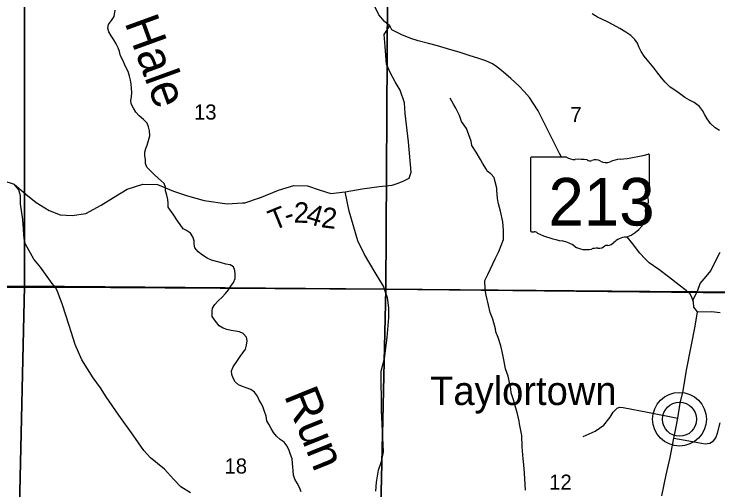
# Model space of a CAD drawing. Extents: x 2.1 to 8.9, y 14.1 to 20.9.
# Drawn here: x 3.51 to 5.459, y 18.588 to 19.907 of the extents above; entities that cross this region are included whole.
import ezdxf

# ---------------------------------------------------------------- set-up
doc = ezdxf.new("R2010")
doc.units = 0
for name, color, linetype in [('Default', 7, 'Continuous'), ('GM_X_City_Street', 7, 'Continuous'), ('GM_X_County_Road', 7, 'Continuous'), ('GM_X_County_Road_Text', 7, 'Continuous'), ('GM_X_Interchange_Ramps', 7, 'Continuous'), ('GM_X_Major_River', 7, 'Continuous'), ('GM_X_Minor_River_Text', 7, 'Continuous'), ('GM_X_Rail_Line_Text', 7, 'Continuous'), ('GM_X_Section_Text', 7, 'Continuous'), ('GM_X_State_Route', 7, 'Continuous'), ('GM_X_State_Shield', 7, 'Continuous'), ('GM_X_Township_Text', 7, 'Continuous'), ('PV_P_Text', 7, 'Continuous'), ('TX_P_Misc', 7, 'Continuous')]:
    doc.layers.add(name, color=color, linetype=linetype)

msp = doc.modelspace()

# ---------------------------------------------------------------- linework, layer by layer
at = {"layer": 'Default'}
for p, q in [((3.624, 19.1497), (2.7675, 19.1488)), ((2.7675, 19.1488), (3.624, 19.1497)), ((4.5355, 19.1447), (3.624, 19.1497)), ((3.624, 19.1497), (4.5355, 19.1447)), ((5.3758, 19.1372), (4.5355, 19.1447)), ((4.5355, 19.1447), (5.3758, 19.1372)), ((5.4005, 19.1369), (5.3758, 19.1372)), ((5.3758, 19.1372), (5.4005, 19.1369)), ((6.8944, 19.1204), (5.4005, 19.1369)), ((5.4005, 19.1369), (6.8944, 19.1204))]:
    msp.add_line(p, q, dxfattribs=at)
at = {"layer": 'GM_X_City_Street'}
for p, q in [((4.5343, 19.85), (4.5505, 19.8741)), ((4.5377, 19.8167), (4.5343, 19.85)), ((4.5414, 19.7683), (4.5377, 19.8167)), ((4.5515, 19.7444), (4.5414, 19.7683)), ((4.5655, 19.7188), (4.5515, 19.7444)), ((4.579, 19.6959), (4.5655, 19.7188)), ((4.5912, 19.6607), (4.579, 19.6959)), ((4.5924, 19.6316), (4.5912, 19.6607)), ((4.602, 19.553), (4.5924, 19.6316)), ((4.6091, 19.4686), (4.602, 19.553)), ((4.6042, 19.4521), (4.6091, 19.4686)), ((3.4788, 19.4459), (3.5099, 19.4359)), ((3.5099, 19.4359), (3.5418, 19.4081)), ((3.5231, 19.4198), (3.5099, 19.4359)), ((3.823, 19.422), (3.8666, 19.4357)), ((3.8666, 19.4357), (3.9068, 19.4345)), ((3.9068, 19.4345), (3.9511, 19.4163)), ((4.5563, 19.4329), (4.5738, 19.4382)), ((4.5738, 19.4382), (4.589, 19.4446)), ((4.589, 19.4446), (4.6042, 19.4521)), ((3.5277, 19.4029), (3.5231, 19.4198)), ((3.7854, 19.3983), (3.823, 19.422)), ((3.9511, 19.4163), (3.9902, 19.4028)), ((4.1905, 19.3977), (4.2418, 19.4186)), ((4.2418, 19.4186), (4.2847, 19.4319)), ((4.2847, 19.4319), (4.3222, 19.4305)), ((4.3222, 19.4305), (4.3545, 19.4194)), ((4.3545, 19.4194), (4.3867, 19.4098)), ((4.4266, 19.4138), (4.4739, 19.4224)), ((4.4739, 19.4224), (4.5205, 19.429)), ((4.5205, 19.429), (4.5563, 19.4329)), ((3.5279, 19.3809), (3.5277, 19.4029)), ((3.5418, 19.4081), (3.5708, 19.385)), ((3.7508, 19.3774), (3.7854, 19.3983)), ((3.9902, 19.4028), (4.0365, 19.3905)), ((4.1484, 19.3837), (4.1896, 19.3974)), ((4.1896, 19.3974), (4.1905, 19.3977)), ((4.3867, 19.4098), (4.4266, 19.4138)), ((4.438, 19.3608), (4.4266, 19.4138)), ((3.5341, 19.3377), (3.5279, 19.3809)), ((3.5708, 19.385), (3.6066, 19.3627)), ((3.7083, 19.3543), (3.7508, 19.3774)), ((4.0365, 19.3905), (4.0998, 19.3807)), ((4.0998, 19.3807), (4.1426, 19.3833)), ((4.1426, 19.3833), (4.1484, 19.3837)), ((3.6066, 19.3627), (3.6374, 19.3508)), ((4.4614, 19.2783), (4.438, 19.3608)), ((3.5372, 19.2839), (3.5341, 19.3377)), ((3.6374, 19.3508), (3.6708, 19.3485)), ((3.6708, 19.3485), (3.7083, 19.3543)), ((3.5417, 19.2696), (3.5372, 19.2839)), ((4.4801, 19.2408), (4.4614, 19.2783)), ((3.5643, 19.2279), (3.5417, 19.2696)), ((4.5099, 19.1908), (4.4801, 19.2408)), ((5.4511, 19.2205), (5.4655, 19.2473)), ((3.5824, 19.2053), (3.5643, 19.2279)), ((5.439, 19.1957), (5.4511, 19.2205)), ((3.6155, 19.1603), (3.5824, 19.2053)), ((4.5327, 19.1531), (4.5099, 19.1908)), ((5.4265, 19.1795), (5.439, 19.1957)), ((5.41, 19.1598), (5.4265, 19.1795)), ((3.6242, 19.1492), (3.6155, 19.1603)), ((3.6251, 19.1475), (3.6242, 19.1492)), ((3.6286, 19.1408), (3.6251, 19.1475)), ((4.5357, 19.1442), (4.5327, 19.1531)), ((4.5437, 19.1202), (4.5357, 19.1442)), ((5.4022, 19.1393), (5.41, 19.1598)), ((3.6442, 19.1012), (3.6286, 19.1408)), ((5.3893, 19.1136), (5.3985, 19.132)), ((5.3985, 19.132), (5.4007, 19.1364)), ((5.4007, 19.1364), (5.4022, 19.1393)), ((4.5456, 19.1077), (4.5437, 19.1202)), ((4.5479, 19.0923), (4.5456, 19.1077)), ((3.6623, 19.0436), (3.6442, 19.1012)), ((4.5472, 19.0657), (4.5479, 19.0923)), ((4.5425, 19.0104), (4.5472, 19.0657)), ((3.6789, 18.9911), (3.6623, 19.0436)), ((4.5352, 18.9523), (4.5425, 19.0104)), ((3.6974, 18.9488), (3.6789, 18.9911)), ((3.7288, 18.8988), (3.6974, 18.9488)), ((4.5262, 18.9174), (4.5352, 18.9523)), ((4.5268, 18.8092), (4.5262, 18.9174)), ((3.7486, 18.8714), (3.7288, 18.8988)), ((3.7645, 18.8465), (3.7486, 18.8714)), ((3.7994, 18.7953), (3.7645, 18.8465)), ((5.1686, 18.8038), (5.1794, 18.8148)), ((5.1794, 18.8148), (5.1861, 18.8177)), ((5.1861, 18.8177), (5.1964, 18.8164)), ((5.1964, 18.8164), (5.264, 18.8035)), ((3.8396, 18.7396), (3.7994, 18.7953)), ((4.5327, 18.6939), (4.5268, 18.8092)), ((5.1606, 18.7902), (5.1686, 18.8038)), ((5.264, 18.8035), (5.3482, 18.7874)), ((5.1431, 18.768), (5.1606, 18.7902)), ((5.458, 18.7457), (5.4649, 18.7745)), ((5.1185, 18.7508), (5.1431, 18.768)), ((3.8689, 18.6973), (3.8396, 18.7396)), ((5.086, 18.7361), (5.1185, 18.7508)), ((5.3368, 18.7319), (5.3784, 18.7243)), ((5.4463, 18.7239), (5.4534, 18.7323)), ((5.4534, 18.7323), (5.458, 18.7457)), ((5.3784, 18.7243), (5.4036, 18.7194)), ((5.4036, 18.7194), (5.4232, 18.7162)), ((5.4232, 18.7162), (5.4366, 18.7179)), ((5.4366, 18.7179), (5.4463, 18.7239)), ((3.8879, 18.6771), (3.8689, 18.6973)), ((4.5276, 18.6674), (4.5327, 18.6939)), ((3.9259, 18.6462), (3.8879, 18.6771)), ((4.5193, 18.6431), (4.5276, 18.6674)), ((3.9509, 18.618), (3.9259, 18.6462)), ((4.5132, 18.6095), (4.5193, 18.6431)), ((3.9711, 18.5969), (3.9509, 18.618)), ((3.998, 18.5798), (3.9711, 18.5969)), ((4.5117, 18.5848), (4.5132, 18.6095))]:
    msp.add_line(p, q, dxfattribs=at)
at = {"layer": 'GM_X_County_Road'}
for p, q in [((5.2696, 19.4105), (5.2696, 19.5152)), ((4.94, 19.5068), (4.94, 19.3066)), ((5.0398, 19.5102), (4.9432, 19.5102)), ((5.2695, 19.4105), (5.2696, 19.4105))]:
    msp.add_line(p, q, dxfattribs=at)
for centre, major_axis, start_param, end_param in [((5.1522, 19.783), (0.3495, 0), 4.814394, 5.042369), ((5.2659, 19.5156), (0.00367, 0), 6.141152, 7.989035), ((4.9438, 19.5072), (0.00382, 0), 1.712693, 3.28349), ((5.0627, 19.5334), (0.037, 0), 4.042523, 4.731795), ((5.075, 19.3979), (0.133, 0), 1.404758, 1.657858), ((5.1052, 19.5082), (0.0107, 0), 3.836095, 5.185415), ((5.1209, 19.4851), (0.0222, 0), 0.950623, 2.079405), ((5.1496, 19.5168), (0.0267, 0), 4.081561, 5.145723), ((5.1968, 19.4491), (0.0703, 0), 1.699011, 2.107814), ((5.2687, 19.4028), (0.00568, 0), 1.883978, 3.671073), ((5.2326, 19.3896), (0.0341, 0), 5.934695, 6.695948), ((5.2657, 19.4101), (0.00393, 0), 5.05454, 6.418171), ((5.2827, 19.3667), (0.0248, 0), 2.387724, 3.262537), ((5.1717, 19.3533), (0.0874, 0), 5.101752, 6.440018), ((4.9438, 19.3062), (0.00385, 0), 3.00124, 4.508301), ((4.9444, 19.3267), (0.0294, 0), 4.665946, 4.897461), ((4.9504, 19.2951), (0.0106, 0), 0.519207, 1.627899), ((5.0842, 19.4749), (0.2524, 0), 4.195997, 4.488961), ((5.009, 19.2167), (0.079, 0), 0.823519, 1.323587), ((5.2086, 19.2505), (0.0479, 0), 1.647645, 2.488434), ((5.0944, 19.2941), (0.0501, 0), 4.026481, 4.996735), ((5.127, 19.2791), (0.0267, 0), 4.691044, 5.507374), ((5.1512, 19.2597), (0.00752, 0), 1.147584, 2.315152), ((5.1479, 19.2872), (0.0282, 0), 4.937069, 5.64225), ((5.1233, 19.2249), (0.0412, 0), 1.495662, 1.94098)]:
    msp.add_ellipse(centre, major_axis=major_axis, ratio=0.8, start_param=start_param, end_param=end_param, dxfattribs=at)
at = {"layer": 'GM_X_Interchange_Ramps'}
for p, q in [((3.5383, 20.1501), (3.5387, 19.1524)), ((3.5387, 19.1524), (3.5383, 20.1501)), ((4.5449, 20.1449), (4.5388, 19.1444)), ((4.5388, 19.1444), (4.5449, 20.1449)), ((3.5387, 19.1524), (2.5274, 19.148)), ((2.5274, 19.148), (3.5387, 19.1524)), ((3.5387, 19.1524), (3.5154, 18.1224)), ((3.5154, 18.1224), (3.5387, 19.1524)), ((4.5388, 19.1444), (3.5387, 19.1524)), ((3.5387, 19.1524), (4.5388, 19.1444)), ((4.5388, 19.1444), (4.5166, 18.1148)), ((4.5166, 18.1148), (4.5388, 19.1444)), ((5.5458, 19.1336), (4.5388, 19.1444)), ((4.5388, 19.1444), (5.5458, 19.1336))]:
    msp.add_line(p, q, dxfattribs=at)
at = {"layer": 'GM_X_Rail_Line_Text'}
for p, q in [((4.5194, 19.9047), (4.4987, 19.9491)), ((4.5357, 19.8864), (4.5194, 19.9047)), ((4.5505, 19.8741), (4.5357, 19.8864)), ((4.5554, 19.8631), (4.5505, 19.8741)), ((4.5837, 19.8496), (4.5554, 19.8631)), ((4.6085, 19.8394), (4.5837, 19.8496)), ((4.6284, 19.8326), (4.6085, 19.8394)), ((4.6574, 19.8248), (4.6284, 19.8326)), ((4.6821, 19.8184), (4.6574, 19.8248)), ((4.7103, 19.8103), (4.6821, 19.8184)), ((4.7447, 19.7999), (4.7103, 19.8103)), ((4.7725, 19.791), (4.7447, 19.7999)), ((4.7943, 19.7846), (4.7725, 19.791)), ((4.816, 19.7774), (4.7943, 19.7846)), ((4.8348, 19.7686), (4.816, 19.7774)), ((4.8467, 19.7601), (4.8348, 19.7686)), ((4.8655, 19.7457), (4.8467, 19.7601)), ((4.8856, 19.7286), (4.8655, 19.7457)), ((4.9084, 19.707), (4.8856, 19.7286)), ((4.9227, 19.6918), (4.9084, 19.707)), ((4.9367, 19.6753), (4.9227, 19.6918)), ((4.9476, 19.66), (4.9367, 19.6753)), ((4.9609, 19.6382), (4.9476, 19.66)), ((4.9778, 19.6055), (4.9609, 19.6382)), ((5.0011, 19.5593), (4.9778, 19.6055)), ((5.02, 19.5205), (5.0011, 19.5593)), ((5.0253, 19.5102), (5.02, 19.5205)), ((5.2224, 19.2709), (5.2072, 19.2894)), ((5.243, 19.2439), (5.2224, 19.2709)), ((5.2573, 19.2283), (5.243, 19.2439)), ((5.2689, 19.2179), (5.2573, 19.2283)), ((5.295, 19.1986), (5.2689, 19.2179)), ((5.3216, 19.1787), (5.295, 19.1986)), ((5.3516, 19.1557), (5.3216, 19.1787)), ((5.3712, 19.1409), (5.3516, 19.1557)), ((5.376, 19.1366), (5.3712, 19.1409)), ((5.3809, 19.1324), (5.376, 19.1366)), ((5.3867, 19.1226), (5.3809, 19.1324)), ((5.3893, 19.1136), (5.3867, 19.1226)), ((5.3908, 19.1083), (5.3893, 19.1136)), ((5.3926, 19.0942), (5.3908, 19.1083)), ((5.4022, 19.0815), (5.3926, 19.0942)), ((5.3956, 19.0421), (5.4022, 19.0815)), ((5.385, 18.9861), (5.3956, 19.0421)), ((5.372, 18.9201), (5.385, 18.9861)), ((5.3624, 18.8625), (5.372, 18.9201)), ((5.3545, 18.8288), (5.3624, 18.8625)), ((5.3482, 18.7874), (5.3545, 18.8288)), ((5.3422, 18.7584), (5.3482, 18.7874)), ((5.3368, 18.7319), (5.3422, 18.7584)), ((5.3262, 18.6778), (5.3368, 18.7319)), ((5.3153, 18.63), (5.3262, 18.6778)), ((5.304, 18.5723), (5.3153, 18.63))]:
    msp.add_line(p, q, dxfattribs=at)
at = {"layer": 'GM_X_State_Route'}
for radius in [0.0744, 0.0472]:
    msp.add_circle((5.3524, 18.7841), radius, dxfattribs=at)
at = {"layer": 'GM_X_State_Shield'}
for p, q in [((5.4022, 19.0815), (5.441, 19.0825)), ((5.441, 19.0825), (5.4647, 19.0796))]:
    msp.add_line(p, q, dxfattribs=at)
at = {"layer": 'GM_X_Township_Text'}
msp.add_line((5.3524, 18.7841), (5.3524, 18.7841), dxfattribs=at)
at = {"layer": 'TX_P_Misc'}
for p, q in [((3.7871, 19.9004), (3.7896, 19.9176)), ((5.1255, 19.8986), (5.1104, 19.9072)), ((3.7715, 19.8778), (3.7799, 19.8887)), ((3.7799, 19.8887), (3.7871, 19.9004)), ((5.139, 19.8918), (5.1255, 19.8986)), ((5.1529, 19.8854), (5.139, 19.8918)), ((5.1692, 19.8767), (5.1529, 19.8854)), ((3.7695, 19.8679), (3.7715, 19.8778)), ((3.7725, 19.8577), (3.7695, 19.8679)), ((5.1874, 19.8667), (5.1692, 19.8767)), ((5.2036, 19.8569), (5.1874, 19.8667)), ((3.7786, 19.8461), (3.7725, 19.8577)), ((3.7858, 19.8353), (3.7786, 19.8461)), ((5.2176, 19.8475), (5.2036, 19.8569)), ((5.229, 19.8364), (5.2176, 19.8475)), ((3.7922, 19.8241), (3.7858, 19.8353)), ((3.7975, 19.8129), (3.7922, 19.8241)), ((5.2358, 19.8264), (5.229, 19.8364)), ((5.2403, 19.8159), (5.2358, 19.8264)), ((3.8012, 19.8027), (3.7975, 19.8129)), ((5.246, 19.8027), (5.2403, 19.8159)), ((3.8046, 19.791), (3.8012, 19.8027)), ((3.8111, 19.7791), (3.8046, 19.791)), ((5.2544, 19.7901), (5.246, 19.8027)), ((5.2674, 19.7741), (5.2544, 19.7901)), ((3.8156, 19.7678), (3.8111, 19.7791)), ((3.8205, 19.7581), (3.8156, 19.7678)), ((5.2813, 19.7574), (5.2674, 19.7741)), ((3.8254, 19.7476), (3.8205, 19.7581)), ((3.8292, 19.7351), (3.8254, 19.7476)), ((5.2928, 19.7426), (5.2813, 19.7574)), ((3.8318, 19.7238), (3.8292, 19.7351)), ((5.3023, 19.7304), (5.2928, 19.7426)), ((5.3129, 19.7178), (5.3023, 19.7304)), ((3.8337, 19.7121), (3.8318, 19.7238)), ((3.8352, 19.7019), (3.8337, 19.7121)), ((5.3267, 19.7045), (5.3129, 19.7178)), ((3.8348, 19.6771), (3.836, 19.6893)), ((3.836, 19.6893), (3.8352, 19.7019)), ((5.3426, 19.6936), (5.3267, 19.7045)), ((5.3558, 19.6837), (5.3426, 19.6936)), ((3.8332, 19.6676), (3.8348, 19.6771)), ((3.8343, 19.6577), (3.8332, 19.6676)), ((4.7268, 19.657), (4.7171, 19.6739)), ((5.3675, 19.6754), (5.3558, 19.6837)), ((5.3803, 19.6685), (5.3675, 19.6754)), ((5.3934, 19.6617), (5.3803, 19.6685)), ((3.84, 19.6461), (3.8343, 19.6577)), ((4.7327, 19.6457), (4.7268, 19.657)), ((5.4082, 19.6508), (5.3934, 19.6617)), ((5.4165, 19.64), (5.4082, 19.6508)), ((3.8471, 19.6353), (3.84, 19.6461)), ((3.8562, 19.6246), (3.8471, 19.6353)), ((4.7429, 19.6257), (4.7327, 19.6457)), ((5.423, 19.6273), (5.4165, 19.64)), ((3.868, 19.6143), (3.8562, 19.6246)), ((3.8785, 19.6043), (3.868, 19.6143)), ((4.7492, 19.6095), (4.7429, 19.6257)), ((4.7624, 19.5895), (4.7492, 19.6095)), ((5.4287, 19.6161), (5.423, 19.6273)), ((5.4382, 19.6038), (5.4287, 19.6161)), ((3.8823, 19.5942), (3.8785, 19.6043)), ((3.8845, 19.5836), (3.8823, 19.5942)), ((4.7755, 19.5548), (4.7624, 19.5895)), ((5.4511, 19.5917), (5.4382, 19.6038)), ((5.4631, 19.5837), (5.4511, 19.5917)), ((3.8853, 19.5692), (3.8845, 19.5836)), ((3.8778, 19.5439), (3.8816, 19.5561)), ((3.8816, 19.5561), (3.8853, 19.5692)), ((4.7776, 19.5427), (4.7755, 19.5548)), ((3.8715, 19.5243), (3.8746, 19.5343)), ((3.8746, 19.5343), (3.8778, 19.5439)), ((4.7897, 19.5242), (4.7776, 19.5427)), ((3.8718, 19.5144), (3.8715, 19.5243)), ((3.8733, 19.5034), (3.8718, 19.5144)), ((4.801, 19.5035), (4.7897, 19.5242)), ((3.874, 19.4928), (3.8733, 19.5034)), ((3.8774, 19.483), (3.874, 19.4928)), ((4.8065, 19.4933), (4.801, 19.5035)), ((4.8181, 19.4764), (4.8065, 19.4933)), ((3.8868, 19.473), (3.8774, 19.483)), ((3.8978, 19.4624), (3.8868, 19.473)), ((4.8197, 19.4719), (4.8181, 19.4764)), ((3.9088, 19.4524), (3.8978, 19.4624)), ((4.83, 19.4645), (4.8197, 19.4719)), ((4.8393, 19.4536), (4.83, 19.4645)), ((4.841, 19.4453), (4.8393, 19.4536)), ((3.9256, 19.4374), (3.9088, 19.4524)), ((3.929, 19.4268), (3.9256, 19.4374)), ((4.8462, 19.4245), (4.841, 19.4453)), ((3.9293, 19.4166), (3.929, 19.4268)), ((3.9331, 19.4045), (3.9293, 19.4166)), ((4.8464, 19.418), (4.8462, 19.4245)), ((4.8477, 19.4081), (4.8464, 19.418)), ((3.9357, 19.3932), (3.9331, 19.4045)), ((4.8486, 19.396), (4.8477, 19.4081)), ((4.8508, 19.3808), (4.8486, 19.396)), ((3.9364, 19.3826), (3.9357, 19.3932)), ((3.936, 19.3719), (3.9364, 19.3826)), ((4.8568, 19.3608), (4.8508, 19.3808)), ((3.9428, 19.3622), (3.936, 19.3719)), ((3.9503, 19.3526), (3.9428, 19.3622)), ((4.863, 19.3312), (4.8568, 19.3608)), ((3.9627, 19.3339), (3.9503, 19.3526)), ((3.9698, 19.3239), (3.9627, 19.3339)), ((3.9778, 19.312), (3.9698, 19.3239)), ((4.8653, 19.3073), (4.863, 19.3312)), ((3.9875, 19.3066), (3.9778, 19.312)), ((3.9987, 19.3001), (3.9875, 19.3066)), ((4.0047, 19.2896), (3.9987, 19.3001)), ((4.8647, 19.2818), (4.8653, 19.3073)), ((4.0081, 19.2787), (4.0047, 19.2896)), ((4.0088, 19.2688), (4.0081, 19.2787)), ((4.852, 19.2489), (4.8647, 19.2818)), ((4.0106, 19.2586), (4.0088, 19.2688)), ((4.0197, 19.2483), (4.0106, 19.2586)), ((4.0314, 19.2387), (4.0197, 19.2483)), ((4.0442, 19.2308), (4.0314, 19.2387)), ((4.8422, 19.2283), (4.852, 19.2489)), ((4.0565, 19.2251), (4.0442, 19.2308)), ((4.0738, 19.2199), (4.0565, 19.2251)), ((4.0845, 19.2172), (4.0738, 19.2199)), ((4.829, 19.201), (4.8422, 19.2283)), ((4.0964, 19.2138), (4.0845, 19.2172)), ((4.1079, 19.2115), (4.0964, 19.2138)), ((4.1176, 19.2065), (4.1079, 19.2115)), ((4.1213, 19.1963), (4.1176, 19.2065)), ((4.8218, 19.185), (4.829, 19.201)), ((4.1224, 19.1857), (4.1213, 19.1963)), ((4.1216, 19.1739), (4.1224, 19.1857)), ((4.8134, 19.1689), (4.8218, 19.185)), ((4.1098, 19.1526), (4.117, 19.1631)), ((4.117, 19.1631), (4.1216, 19.1739)), ((4.8146, 19.1438), (4.8134, 19.1689)), ((4.0956, 19.1324), (4.1032, 19.1425)), ((4.1032, 19.1425), (4.1098, 19.1526)), ((4.8175, 19.1279), (4.8146, 19.1438)), ((4.076, 19.1127), (4.086, 19.1226)), ((4.086, 19.1226), (4.0956, 19.1324)), ((4.8236, 19.0998), (4.8175, 19.1279)), ((4.0653, 19.1018), (4.076, 19.1127)), ((4.058, 19.0825), (4.0592, 19.0921)), ((4.0592, 19.0921), (4.0653, 19.1018)), ((4.8282, 19.0802), (4.8236, 19.0998)), ((4.0584, 19.0692), (4.058, 19.0825)), ((4.0675, 19.0554), (4.0584, 19.0692)), ((4.8357, 19.0617), (4.8282, 19.0802)), ((4.0774, 19.0428), (4.0675, 19.0554)), ((4.8429, 19.0348), (4.8357, 19.0617)), ((4.0883, 19.0363), (4.0774, 19.0428)), ((4.0987, 19.0324), (4.0883, 19.0363)), ((4.1109, 19.0298), (4.0987, 19.0324)), ((4.1228, 19.0279), (4.1109, 19.0298)), ((4.1342, 19.026), (4.1228, 19.0279)), ((4.1439, 19.0221), (4.1342, 19.026)), ((4.8439, 19.0261), (4.8429, 19.0348)), ((4.8505, 19.011), (4.8439, 19.0261)), ((4.1533, 19.0113), (4.1439, 19.0221)), ((4.1548, 19.0015), (4.1533, 19.0113)), ((4.8578, 18.9879), (4.8505, 19.011)), ((4.1502, 18.9785), (4.1537, 18.9889)), ((4.1537, 18.9889), (4.1548, 19.0015)), ((4.8614, 18.972), (4.8578, 18.9879)), ((4.1356, 18.9575), (4.1429, 18.9677)), ((4.1429, 18.9677), (4.1502, 18.9785)), ((4.8668, 18.9443), (4.8614, 18.972)), ((4.1163, 18.9295), (4.128, 18.9466)), ((4.128, 18.9466), (4.1356, 18.9575)), ((4.1117, 18.9184), (4.1163, 18.9295)), ((4.8706, 18.9242), (4.8668, 18.9443)), ((4.1125, 18.9077), (4.1117, 18.9184)), ((4.1166, 18.8976), (4.1125, 18.9077)), ((4.8782, 18.9031), (4.8706, 18.9242)), ((4.1215, 18.8875), (4.1166, 18.8976)), ((4.8852, 18.8686), (4.8782, 18.9031)), ((4.1316, 18.8794), (4.1215, 18.8875)), ((4.1424, 18.8745), (4.1316, 18.8794)), ((4.1528, 18.871), (4.1424, 18.8745)), ((4.1651, 18.8664), (4.1528, 18.871)), ((4.8865, 18.8572), (4.8852, 18.8686)), ((4.1756, 18.8588), (4.1651, 18.8664)), ((4.1839, 18.8484), (4.1756, 18.8588)), ((4.8925, 18.8383), (4.8865, 18.8572)), ((4.1888, 18.8371), (4.1839, 18.8484)), ((4.1952, 18.827), (4.1888, 18.8371)), ((4.8994, 18.8152), (4.8925, 18.8383)), ((4.1993, 18.8165), (4.1952, 18.827)), ((4.2031, 18.8056), (4.1993, 18.8165)), ((4.9026, 18.8031), (4.8994, 18.8152)), ((4.2077, 18.7924), (4.2031, 18.8056)), ((4.21, 18.78), (4.2077, 18.7924)), ((4.9083, 18.7789), (4.9026, 18.8031)), ((4.2148, 18.7702), (4.21, 18.78)), ((4.9092, 18.7713), (4.9083, 18.7789)), ((4.9121, 18.7573), (4.9092, 18.7713)), ((4.2213, 18.7586), (4.2148, 18.7702)), ((4.2281, 18.7478), (4.2213, 18.7586)), ((4.9154, 18.7391), (4.9121, 18.7573)), ((4.2368, 18.7374), (4.2281, 18.7478)), ((4.2469, 18.7283), (4.2368, 18.7374)), ((4.9171, 18.7079), (4.9154, 18.7391)), ((4.2578, 18.7202), (4.2469, 18.7283)), ((4.2662, 18.7091), (4.2578, 18.7202)), ((4.2715, 18.6975), (4.2662, 18.7091)), ((4.2749, 18.6862), (4.2715, 18.6975)), ((4.9196, 18.6745), (4.9171, 18.7079)), ((4.2798, 18.6741), (4.2749, 18.6862)), ((4.2809, 18.6624), (4.2798, 18.6741)), ((4.921, 18.6578), (4.9196, 18.6745)), ((4.2816, 18.6521), (4.2809, 18.6624)), ((4.923, 18.6343), (4.921, 18.6578)), ((4.2824, 18.6407), (4.2816, 18.6521)), ((4.2835, 18.629), (4.2824, 18.6407)), ((4.2876, 18.6185), (4.2835, 18.629)), ((4.2941, 18.6069), (4.2876, 18.6185)), ((4.9261, 18.5876), (4.923, 18.6343)), ((4.2998, 18.5945), (4.2941, 18.6069)), ((4.3051, 18.5825), (4.2998, 18.5945))]:
    msp.add_line(p, q, dxfattribs=at)

# ---------------------------------------------------------------- texts
at = {"layer": 'GM_X_County_Road'}
msp.add_text('213', height=0.13184, dxfattribs=at).set_placement((4.9895, 19.3208))
at = {"layer": 'GM_X_County_Road_Text'}
for s, height, p in [('13', 0.04186, (4.008, 19.6144)), ('7', 0.0419, (5.0505, 19.6074)), ('18', 0.04186, (4.0926, 18.6336)), ('12', 0.04186, (4.9917, 18.5889))]:
    msp.add_text(s, height=height, rotation=0, dxfattribs=at).set_placement(p)
at = {"layer": 'GM_X_Major_River'}
msp.add_text('Taylortown', height=0.07898, rotation=0, dxfattribs=at).set_placement((4.6617, 18.8235))
at = {"layer": 'GM_X_Minor_River_Text'}
for s, rotation, p in [('T', 22.064, (4.2282, 19.3064)), ('2', 358.3918, (4.2836, 19.329)), ('4', 343.2619, (4.3146, 19.3287)), ('2', 352.7597, (4.3582, 19.3164)), ('-', 19.4002, (4.267, 19.3221))]:
    msp.add_text(s, height=0.0568, rotation=rotation, dxfattribs=at).set_placement(p)
at = {"layer": 'GM_X_Section_Text'}
msp.add_text('213', height=0.000189, rotation=0, dxfattribs=at).set_placement((5.0342, 19.3796))
for s in ['s', 'r']:
    msp.add_text(s, height=0.000189, dxfattribs=at).set_placement((5.1011, 19.3934))
at = {"layer": 'PV_P_Text'}
for s, height, rotation, p in [('Hale', 0.09469, 289.9705, (3.8149, 19.8837)), ('Run', 0.0947, 291.9594, (4.2566, 18.85))]:
    msp.add_text(s, height=height, rotation=rotation, dxfattribs=at).set_placement(p)

doc.saveas('drawing.dxf')
